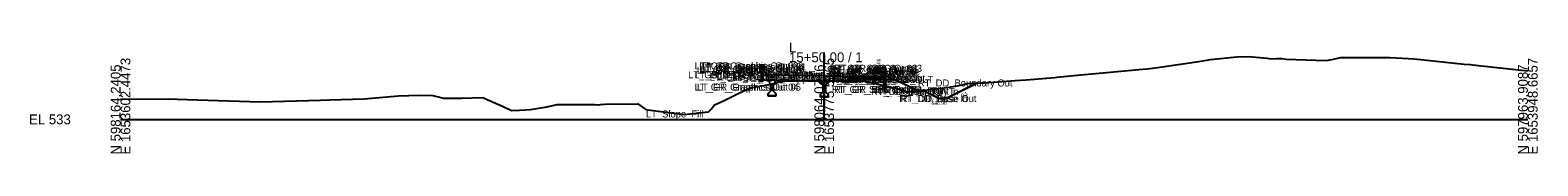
# Model space of a CAD drawing. Extents: x -26 to 403, y -10 to 6021.
# Drawn here: x -25.7 to 402.8, y 3990.3 to 4021.8 of the extents above; entities that cross this region are included whole.
import ezdxf

# ---------------------------------------------------------------- set-up
doc = ezdxf.new("R2010")
doc.units = 0
for name, color, linetype in [('Default', 7, 'Continuous'), ('Exist Cross Section Cell', 7, 'Continuous'), ('Exist XS Ground Line', 7, 'Continuous'), ('Prop CMT Conc Surface', 7, 'Continuous'), ('Prop CMT Concrete Structures', 7, 'Continuous'), ('Prop CMT Ditch DDE', 7, 'Continuous'), ('Prop CMT Guardrail SBG', 7, 'Continuous'), ('Prop CMT Pvmt Course 1', 7, 'Continuous'), ('Prop CMT Pvmt Course 2', 7, 'Continuous'), ('Prop CMT Pvmt Course 3', 7, 'Continuous'), ('Prop CMT Pvmt Course SBG', 7, 'Continuous'), ('Prop CMT Pvmt Surface', 7, 'Continuous'), ('Prop CMT Pvmt Surface Shoulder', 7, 'Continuous'), ('Prop CMT Shld Paved Course 1', 7, 'Continuous'), ('Prop CMT Shld Paved Course 2', 7, 'Continuous'), ('Prop CMT Shld Paved Course 3', 7, 'Continuous'), ('Prop CMT Slope Grass', 7, 'Continuous'), ('Prop CMT Subgrade Earthwork', 7, 'Continuous'), ('Prop XS Ditch Slope Text', 7, 'Continuous'), ('Prop XS Ditch Standard Text', 7, 'Continuous'), ('Prop XS Earthwork Shape', 7, 'Continuous'), ('Prop XS Hydro Elevations', 7, 'Continuous'), ('Prop XS SE Text', 7, 'Continuous'), ('Prop XS Side Slope Text', 7, 'Continuous')]:
    doc.layers.add(name, color=color, linetype=linetype)

msp = doc.modelspace()

# ---------------------------------------------------------------- linework, layer by layer
at = {"layer": 'Exist Cross Section Cell'}
for p, q in [((200, 4000), (200, 4019.04)), ((0, 4000), (200, 4000)), ((200, 4000), (400, 4000))]:
    msp.add_line(p, q, dxfattribs=at)
at = {"layer": 'Exist XS Ground Line'}
msp.add_lwpolyline([(0, 4005.72), (0.13, 4005.72), (13.61, 4005.81), (16.11, 4005.73), (21.8, 4005.51), (39.78, 4004.97), (56.84, 4005.46), (59.36, 4005.53), (69.28, 4005.83), (78.98, 4006.71), (84.86, 4006.86), (88.72, 4006.83), (91.79, 4006.04), (97.02, 4006.01), (102.94, 4006.18), (104.23, 4005.61), (108.59, 4003.72), (111.08, 4002.5), (113.4, 4002.61), (116.51, 4002.77), (121.17, 4003.54), (124.11, 4004.2), (134.81, 4004.19), (135.74, 4004.1), (136.01, 4004.15), (136.46, 4004.22), (137.68, 4004.28), (147, 4004.42), (149.05, 4003.03), (149.27, 4002.78), (150.64, 4002.65), (160.19, 4001.35), (166.18, 4002.08), (167.12, 4002.18), (167.83, 4002.94), (168.86, 4004.09), (171.39, 4005.31), (173.99, 4006.64), (177.87, 4008.5), (179.62, 4009.03), (183.93, 4009.85), (188.14, 4010.85), (192.62, 4010.94), (199.73, 4011.01), (200, 4011.01), (208.01, 4010.98), (211.27, 4010.97), (213.95, 4010.25), (220.34, 4008.81), (222.59, 4008.16), (223.53, 4007.73), (233.41, 4008.84), (237.3, 4009.42), (238.76, 4009.69), (240.86, 4010.2), (246.76, 4010.52), (254.31, 4011), (257.38, 4011.27), (265.57, 4011.88), (266.14, 4011.95), (272.91, 4012.67), (279.22, 4013.22), (290.51, 4014.29), (291.86, 4014.4), (295.4, 4014.8), (305.81, 4016.4), (309.83, 4016.98), (317.24, 4017.8), (320.74, 4017.91), (325.88, 4017.36), (326.91, 4017.24), (328.62, 4017.26), (330.03, 4017.27), (331.34, 4017.09), (339.73, 4016.79), (342.68, 4016.73), (344.31, 4017.04), (346.85, 4017.56), (353.16, 4017.54), (360.79, 4017.58), (367.79, 4017.17), (381.92, 4015.73), (383.66, 4015.55), (384.36, 4015.5), (386.8, 4015.23), (400, 4013.78)], dxfattribs=at)
at = {"layer": 'Prop CMT Conc Surface'}
msp.add_lwpolyline([(213.58, 4012.1), (215.92, 4012.01), (216.58, 4012.35)], dxfattribs=at)
at = {"layer": 'Prop CMT Concrete Structures'}
for points in [[(200, 4012.37), (188, 4012.61), (183.58, 4012.7), (183.57, 4012.95), (182.99, 4013.78), (182.82, 4015.37), (182.08, 4015.37), (182.08, 4011.23)], [(182.08, 4011.23), (188, 4011.11), (200, 4010.87)], [(186.04, 4011.15), (185.21, 4011.17), (184.37, 4011.18)], [(184.37, 4011.18), (184.37, 4010.5)], [(186.04, 4010.5), (186.04, 4011.15)], [(200, 4010.87), (200, 4012.37)], [(200, 4010.87), (200, 4012.37)], [(200, 4012.37), (206.87, 4012.23)], [(206.87, 4010.73), (206.87, 4012.23)], [(213.58, 4012.1), (215.92, 4012.01), (216.58, 4012.35)], [(213.58, 4011.68), (213.58, 4012.1)], [(216.58, 4011.68), (213.58, 4011.68)], [(216.58, 4012.35), (216.58, 4011.68)], [(184.87, 4008.08), (184.12, 4007.33)], [(184.12, 4007.33), (184.12, 4006.67)], [(184.37, 4010.5), (184.87, 4010)], [(184.87, 4010), (184.87, 4008.08)], [(185.54, 4010), (186.04, 4010.5)], [(185.54, 4008.08), (185.54, 4010)], [(186.29, 4007.33), (185.54, 4008.08)], [(186.29, 4006.67), (186.29, 4007.33)], [(199.67, 4007.79), (198.92, 4007.04)], [(198.92, 4007.04), (198.92, 4006.37)], [(200, 4010.87), (199.17, 4010.89)], [(199.17, 4010.89), (199.17, 4010.2)], [(199.17, 4010.2), (199.67, 4009.7)], [(199.67, 4009.7), (199.67, 4007.79)], [(200, 4006.37), (200, 4010.87)], [(200, 4010.87), (200.83, 4010.85)], [(200, 4006.37), (200, 4010.87)], [(206.87, 4010.73), (200, 4010.87)], [(200.83, 4010.2), (200.33, 4009.7)], [(200.33, 4009.7), (200.33, 4007.79)], [(200.33, 4007.79), (201.08, 4007.04)], [(200.83, 4010.85), (200.83, 4010.2)], [(201.08, 4007.04), (201.08, 4006.37)], [(184.12, 4006.67), (185.21, 4006.67), (186.29, 4006.67)], [(198.92, 4006.37), (200, 4006.37)], [(201.08, 4006.37), (200, 4006.37)]]:
    msp.add_lwpolyline(points, dxfattribs=at)
at = {"layer": 'Prop CMT Ditch DDE'}
msp.add_lwpolyline([(226.68, 4008.08), (228.68, 4007.92), (232.71, 4005.9), (234.71, 4005.9), (243.61, 4010.35)], dxfattribs=at)
at = {"layer": 'Prop CMT Guardrail SBG'}
for points in [[(217.52, 4014.51), (216.19, 4014.51), (215.92, 4014.21)], [(215.92, 4014.21), (216.19, 4013.92)], [(216.19, 4013.92), (215.92, 4013.63)], [(215.92, 4013.63), (216.19, 4013.34), (216.85, 4013.34)], [(216.85, 4013.34), (216.85, 4008.51)], [(217.52, 4008.51), (217.52, 4014.51)], [(216.85, 4008.51), (217.52, 4008.51)]]:
    msp.add_lwpolyline(points, dxfattribs=at)
at = {"layer": 'Prop CMT Pvmt Course 1'}
msp.add_lwpolyline([(200, 4012.16), (200, 4012.16), (200, 4012.16), (200, 4012.16)], close=True, dxfattribs=at)
msp.add_lwpolyline([(200, 4012.16), (200, 4012.16), (200, 4012.16), (200, 4012.16)], close=True, dxfattribs=at)
msp.add_lwpolyline([(200, 4012.16), (200, 4012.16), (200, 4012.16), (200, 4012.16)], close=True, dxfattribs=at)
for points in [[(206.87, 4012.23), (212, 4012.13)], [(206.87, 4012.02), (206.87, 4012.23)], [(206.87, 4012.02), (206.87, 4012.23)], [(212, 4011.92), (206.87, 4012.02)], [(212, 4012.13), (212, 4011.92)]]:
    msp.add_lwpolyline(points, dxfattribs=at)
at = {"layer": 'Prop CMT Pvmt Course 2'}
for points in [[(206.87, 4011.82), (206.87, 4012.02)], [(206.87, 4012.02), (212, 4011.92)], [(206.87, 4011.82), (206.87, 4012.02)], [(212, 4011.71), (206.87, 4011.82)], [(212, 4011.92), (212, 4011.71)]]:
    msp.add_lwpolyline(points, dxfattribs=at)
at = {"layer": 'Prop CMT Pvmt Course 3'}
for points in [[(206.87, 4011.82), (212, 4011.71)], [(206.87, 4011.48), (206.87, 4011.82)], [(206.87, 4011.48), (206.87, 4011.82)], [(212, 4011.38), (206.87, 4011.48)], [(212, 4011.71), (212, 4011.38)]]:
    msp.add_lwpolyline(points, dxfattribs=at)
at = {"layer": 'Prop CMT Pvmt Course SBG'}
for points in [[(213.58, 4011.68), (216.58, 4011.68), (217.08, 4011.68), (217.42, 4011.35)], [(213.58, 4011.35), (213.58, 4011.68)], [(217.42, 4011.35), (213.58, 4011.35)]]:
    msp.add_lwpolyline(points, dxfattribs=at)
at = {"layer": 'Prop CMT Pvmt Surface'}
msp.add_lwpolyline([(206.87, 4012.23), (212, 4012.13)], dxfattribs=at)
at = {"layer": 'Prop CMT Pvmt Surface Shoulder'}
msp.add_lwpolyline([(212, 4012.13), (213.58, 4012.1)], dxfattribs=at)
at = {"layer": 'Prop CMT Shld Paved Course 1'}
for points in [[(212, 4012.13), (213.58, 4012.1)], [(212, 4011.92), (212, 4012.13)], [(213.58, 4011.89), (212, 4011.92)], [(213.58, 4012.1), (213.58, 4011.89)]]:
    msp.add_lwpolyline(points, dxfattribs=at)
at = {"layer": 'Prop CMT Shld Paved Course 2'}
for points in [[(212, 4011.92), (213.58, 4011.89)], [(212, 4011.71), (212, 4011.92)], [(213.58, 4011.68), (212, 4011.71)], [(213.58, 4011.89), (213.58, 4011.68)]]:
    msp.add_lwpolyline(points, dxfattribs=at)
at = {"layer": 'Prop CMT Shld Paved Course 3'}
for points in [[(212, 4011.71), (213.58, 4011.68)], [(212, 4011.38), (212, 4011.71)], [(213.58, 4011.35), (212, 4011.38)], [(213.58, 4011.68), (213.58, 4011.35)]]:
    msp.add_lwpolyline(points, dxfattribs=at)
at = {"layer": 'Prop CMT Slope Grass'}
msp.add_lwpolyline([(216.58, 4012.35), (217.35, 4012.75), (226.68, 4008.08)], dxfattribs=at)
at = {"layer": 'Prop CMT Subgrade Earthwork'}
msp.add_line((206.87, 4010.73), (206.87, 4012.23), dxfattribs=at)
for points in [[(206.87, 4011.48), (212, 4011.38)], [(212, 4011.38), (213.58, 4011.35)], [(213.58, 4011.35), (213.58, 4011.35)], [(213.58, 4011.35), (217.42, 4011.35), (220.15, 4011.35)]]:
    msp.add_lwpolyline(points, dxfattribs=at)
at = {"layer": 'Prop XS Earthwork Shape'}
for points in [[(186.04, 4011.15), (188, 4011.11), (195.27, 4010.96), (192.62, 4010.94), (188.14, 4010.85), (185.85, 4010.31), (186.04, 4010.5)], [(206.87, 4010.98), (206.87, 4011.48), (212, 4011.38), (213.58, 4011.35), (217.42, 4011.35), (220.15, 4011.35), (226.68, 4008.08), (223.53, 4007.73), (222.59, 4008.16), (220.34, 4008.81), (213.95, 4010.25), (211.27, 4010.97), (208.01, 4010.98)], [(184.81, 4010.06), (185.85, 4010.31), (185.54, 4010), (185.54, 4008.08), (186.29, 4007.33), (186.29, 4006.67), (185.21, 4006.67), (184.12, 4006.67), (184.12, 4007.33), (184.87, 4008.08), (184.87, 4010)], [(195.27, 4010.96), (199.17, 4010.89), (200, 4010.87), (200, 4011.01), (199.73, 4011.01)], [(199.17, 4010.89), (200, 4010.87), (200, 4006.37), (198.92, 4006.37), (198.92, 4007.04), (199.67, 4007.79), (199.67, 4009.7), (199.17, 4010.2)], [(200.83, 4010.85), (200, 4010.87), (200, 4011.01), (206.87, 4010.98), (206.87, 4010.73)], [(200.83, 4010.85), (200, 4010.87), (200, 4006.37), (201.08, 4006.37), (201.08, 4007.04), (200.33, 4007.79), (200.33, 4009.7), (200.83, 4010.2)], [(240.86, 4010.2), (243.61, 4010.35), (234.71, 4005.9), (232.71, 4005.9), (228.68, 4007.92), (226.68, 4008.08), (233.41, 4008.84), (237.3, 4009.42), (238.76, 4009.69)]]:
    msp.add_lwpolyline(points, close=True, dxfattribs=at)

# ---------------------------------------------------------------- texts
at = {"layer": 'Default'}
for s, height, p in [('LT_GR_Graphics Out 03', 2, (163.15, 4014.18)), ('LT_GR_Graphics Out 02', 2, (164.48, 4014.18)), ('LT_GR_Graphics Out 09', 2, (164.48, 4013.6)), ('LT_GR_Graphics Out 08', 2, (164.75, 4013.31)), ('LT_GR_Graphics Out 01', 2, (165.32, 4013.89)), ('RT_GR_SBG Out 02', 2, (201.49, 4013.51)), ('RT_GR_SBG Out 03', 2, (202.83, 4013.51)), ('LT_GS_OS_GR_Face_Graphics', 2, (161.31, 4011.68)), ('LT_Sub_Trench_Out_DLT', 2, (163.15, 4011.63)), ('LT_GR_Graphics Out 06', 2, (163.77, 4013.02)), ('LT_GR_Graphics Out 07', 2, (164.48, 4013.02)), ('LT_Sub_Trench_Out', 2, (167.47, 4010.96)), ('LT_PS3_Shelf_Out', 2, (169.58, 4011.28)), ('LT_GS_OS_CTL', 2, (170.22, 4011.56)), ('LT_PS3_OEOP', 2, (173.83, 4011.28)), ('LT_PS2_OEOP', 2, (174.03, 4011.49)), ('LT_PS1_OEOP', 2, (174.8, 4011.69)), ('LT_Sub_OEOT', 2, (178.08, 4010.86)), ('LT_PV2_OEOT', 2, (178.17, 4011.4)), ('LT_PV3_OEOT', 2, (178.17, 4011.19)), ('LT_PV1_OEOT', 2, (178.74, 4011.61)), ('RT_Sub_OEEOP', 2, (189.17, 4010.62)), ('LT_Sub_OEEOP', 2, (189.21, 4010.62)), ('RT_PV2_OEEOP', 2, (189.26, 4011.16)), ('RT_PV3_OEEOP', 2, (189.26, 4010.95)), ('LT_PV2_OEEOP', 2, (189.31, 4011.16)), ('LT_PV3_OEEOP', 2, (189.31, 4010.95)), ('RT_Seek SS Fill O', 2, (189.44, 4011.37)), ('RT_PV1_OEEOP', 2, (189.83, 4011.16)), ('LT_PV1_OEEOP', 2, (189.87, 4011.16)), ('RT_PV2_IEEOP', 2, (189.91, 4011.16)), ('LT_PV2_IEEOP', 2, (189.95, 4011.16)), ('RT_PV1_IEEOP', 2, (190.47, 4011.16)), ('LT_PV1_IEEOP', 2, (190.52, 4011.16)), ('PV2_PGL', 2, (193.91, 4011.16)), ('PV1_PGL', 2, (194.47, 4011.37)), ('RT_Sub_OEOP_SBG', 2, (199.99, 4010.35)), ('RT_SBG_C1 Shelf Out', 2, (201.18, 4010.68)), ('RT_GR_SBG Out 08', 2, (201.22, 4012.63)), ('RT_GR_SBG Out 09', 2, (201.49, 4012.92)), ('RT_GR_SBG Out 07', 2, (201.49, 4012.34)), ('RT_GR_SBG Out 01', 2, (201.79, 4013.21)), ('RT_Sub_OEOT', 2, (202.03, 4010.38)), ('RT_GR_SBG Out 06', 2, (202.11, 4012.34)), ('RT_PV2_OEOT', 2, (202.13, 4010.92)), ('RT_PV3_OEOT', 2, (202.13, 4010.71)), ('RT_PV1_OEOT', 2, (202.69, 4011.13)), ('RT_CG_Bot_IE', 2, (203.45, 4010.68)), ('RT_Sub_OEOP', 2, (203.65, 4010.35)), ('RT_PS2_OEOP', 2, (203.77, 4010.89)), ('RT_PS3_OEOP', 2, (203.77, 4010.68)), ('RT_CG_Top_Gut', 2, (204.11, 4011.01)), ('RT_PS1_OEOP', 2, (204.34, 4011.1)), ('RT_Sub_SBG Out', 2, (204.55, 4010.35)), ('RT_CG_Top_BOC', 2, (204.82, 4011.35)), ('RT_CG_Bot_BOC', 2, (204.85, 4010.68)), ('RT_GS_OS_CTL', 2, (206.68, 4011.75)), ('RT_Sub_OSS_DLT', 2, (207.5, 4010.35)), ('RT_DD_Boundary Out', 2, (226.63, 4009.35)), ('LT_GR_Graphics Out 04', 2, (163.15, 4008.18)), ('LT_GR_Graphics Out 05', 2, (163.81, 4008.18)), ('RT_GR_SBG Out 05', 2, (202.16, 4007.51)), ('RT_GR_SBG Out 04', 2, (202.83, 4007.51)), ('RT_DD_Boundary In', 2, (213.32, 4006.92)), ('RT_SS_Fill_Point', 2, (214.31, 4007.08)), ('RT_Slope_Fill', 2, (217.15, 4007.08)), ('RT_DD_Base In', 2, (221.37, 4004.9)), ('RT_DD_Base Out', 2, (221.75, 4004.9)), ('LT_Slope_Fill', 2, (149.32, 4000.54)), ('-', 0.0001, (0, 4000))]:
    msp.add_text(s, height=height, dxfattribs=at).set_placement(p)
at = {"layer": 'Exist Cross Section Cell'}
for s, p in [('L', (190, 4019.04)), ('15+50.00 / 1', (190, 4016.24)), ('EL 533', (-26, 3998.6))]:
    msp.add_text(s, height=2.8, dxfattribs=at).set_placement(p)
for s, p in [('N 598164.2405', (0, 3990)), ('E 1653602.4473', (2.8, 3990)), ('N 598064.0746', (200, 3990)), ('E 1653775.5565', (202.8, 3990)), ('N 597963.9087', (400, 3990)), ('E 1653948.6657', (402.8, 3990))]:
    msp.add_text(s, height=2.8, rotation=90, dxfattribs=at).set_placement(p)
at = {"layer": 'Prop XS Ditch Slope Text'}
for rotation, p in [(26.5651, (239.23, 4006.2)), (333.4349, (229.2, 4005.7))]:
    msp.add_text('2:1', height=1, rotation=rotation, dxfattribs=at).set_placement(p)
at = {"layer": 'Prop XS Ditch Standard Text'}
msp.add_text('538.90', height=1, dxfattribs=at).set_placement((230.57, 4004.15))
at = {"layer": 'Prop XS Hydro Elevations'}
msp.add_text('545.01', height=1, rotation=90, dxfattribs=at).set_placement((215.92, 4013.01))
at = {"layer": 'Prop XS SE Text'}
for p in [(192.27, 4013.53), (192.27, 4013.53), (204.27, 4013.29)]:
    msp.add_text('0.020', height=1, rotation=358.8542, dxfattribs=at).set_placement(p)
at = {"layer": 'Prop XS Side Slope Text'}
msp.add_text('2:1', height=1, rotation=333.4349, dxfattribs=at).set_placement((221.64, 4011.44))

doc.saveas('drawing.dxf')
